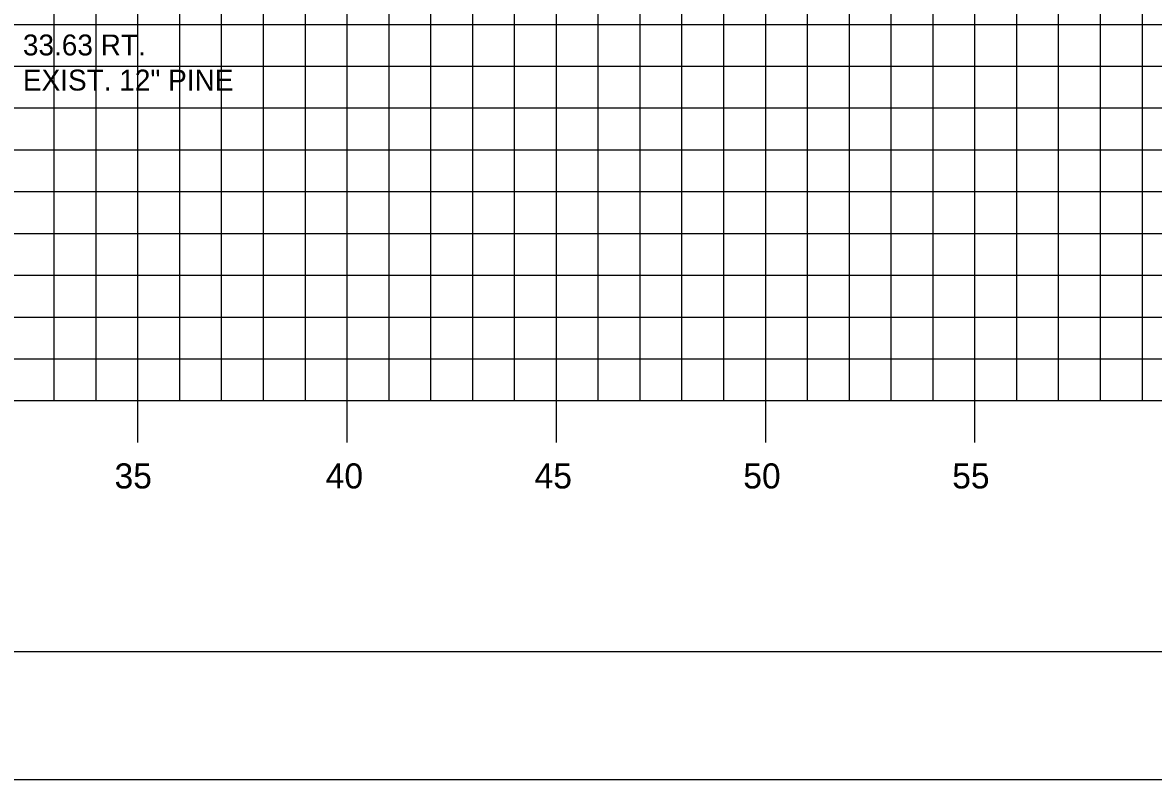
# Model space of a CAD drawing. Extents: x 859352 to 859522, y 366268 to 366378.
# Drawn here: x 859467.37 to 859494.39, y 366268.18 to 366286.28 of the extents above; entities that cross this region are included whole.
import ezdxf

# ---------------------------------------------------------------- set-up
doc = ezdxf.new("R2010")
doc.units = 0
for name, color, linetype in [('BORDER', 7, 'Continuous'), ('D_Text_Monospaced', 7, 'Continuous'), ('H_V ANNOTATION', 7, 'Continuous'), ('MAJOR', 7, 'Continuous'), ('MINOR', 7, 'Continuous'), ('PLOT BOUNDARY', 7, 'Continuous')]:
    doc.layers.add(name, color=color, linetype=linetype)

msp = doc.modelspace()

# ---------------------------------------------------------------- linework, layer by layer
at = {"layer": 'BORDER'}
msp.add_line((859360.13, 366271.236), (859520.13, 366271.236), dxfattribs=at)
at = {"layer": 'MAJOR'}
for p, q in [((859470.129, 366277.236), (859470.129, 366297.236)), ((859475.129, 366277.236), (859475.129, 366297.236)), ((859480.129, 366277.236), (859480.129, 366297.236)), ((859485.129, 366277.236), (859485.129, 366297.236)), ((859490.129, 366277.236), (859490.129, 366297.236)), ((859365.129, 366282.236), (859505.129, 366282.236)), ((859365.129, 366277.236), (859505.129, 366277.236)), ((859365.129, 366277.236), (859505.129, 366277.236)), ((859470.129, 366276.234), (859470.129, 366277.236)), ((859475.129, 366276.234), (859475.129, 366277.236)), ((859480.129, 366276.234), (859480.129, 366277.236)), ((859485.129, 366276.234), (859485.129, 366277.236)), ((859490.129, 366276.234), (859490.129, 366277.236))]:
    msp.add_line(p, q, dxfattribs=at)
at = {"layer": 'MINOR'}
for p, q in [((859468.129, 366277.236), (859468.129, 366297.236)), ((859469.129, 366277.236), (859469.129, 366297.236)), ((859471.129, 366277.236), (859471.129, 366297.236)), ((859472.129, 366277.236), (859472.129, 366297.236)), ((859473.129, 366277.236), (859473.129, 366297.236)), ((859474.129, 366277.236), (859474.129, 366297.236)), ((859476.129, 366277.236), (859476.129, 366297.236)), ((859477.129, 366277.236), (859477.129, 366297.236)), ((859478.129, 366277.236), (859478.129, 366297.236)), ((859479.129, 366277.236), (859479.129, 366297.236)), ((859481.129, 366277.236), (859481.129, 366297.236)), ((859482.129, 366277.236), (859482.129, 366297.236)), ((859483.129, 366277.236), (859483.129, 366297.236)), ((859484.129, 366277.236), (859484.129, 366297.236)), ((859486.129, 366277.236), (859486.129, 366297.236)), ((859487.129, 366277.236), (859487.129, 366297.236)), ((859488.129, 366277.236), (859488.129, 366297.236)), ((859489.129, 366277.236), (859489.129, 366297.236)), ((859491.129, 366277.236), (859491.129, 366297.236)), ((859492.129, 366277.236), (859492.129, 366297.236)), ((859493.129, 366277.236), (859493.129, 366297.236)), ((859494.129, 366277.236), (859494.129, 366297.236)), ((859365.129, 366286.236), (859505.129, 366286.236)), ((859365.129, 366285.236), (859505.129, 366285.236)), ((859365.129, 366284.236), (859505.129, 366284.236)), ((859365.129, 366283.236), (859505.129, 366283.236)), ((859365.129, 366281.236), (859505.129, 366281.236)), ((859365.129, 366280.236), (859505.129, 366280.236)), ((859365.129, 366279.236), (859505.129, 366279.236)), ((859365.129, 366278.236), (859505.129, 366278.236))]:
    msp.add_line(p, q, dxfattribs=at)
at = {"layer": 'PLOT BOUNDARY'}
msp.add_lwpolyline([(859352.036, 366268.177), (859522.036, 366268.177), (859522.036, 366378.177), (859352.036, 366378.177)], close=True, dxfattribs=at)

# ---------------------------------------------------------------- texts
at = {"layer": 'D_Text_Monospaced'}
for s, height, p in [('33.63 RT.', 0.5, (859467.38, 366285.493)), ('EXIST. 12" PINE', 0.49998, (859467.38, 366284.653))]:
    msp.add_text(s, height=height, dxfattribs=at).set_placement(p)
at = {"layer": 'H_V ANNOTATION'}
for s, p in [('35', (859469.57, 366275.136)), ('40', (859474.616, 366275.136)), ('45', (859479.608, 366275.136)), ('50', (859484.594, 366275.136)), ('55', (859489.586, 366275.136))]:
    msp.add_text(s, height=0.6, dxfattribs=at).set_placement(p)

doc.saveas('drawing.dxf')
